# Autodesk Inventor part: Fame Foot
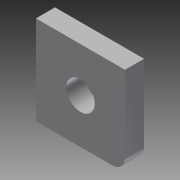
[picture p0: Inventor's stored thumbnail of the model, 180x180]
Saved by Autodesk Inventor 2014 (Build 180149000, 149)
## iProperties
Created: 2007-02
Part Number: Fame Foot
Document SubType Name: Modeling
Designer: Autodesk, Inc.
Density: 7.86 g/cm^3
Material: Steel, Mild
Mass: 135.377 g
Surface Area: 57.0971 cm^2
Volume: 17.2235 cm^3
Appearance: Steel
Title: Plate, Foot
Author: Autodesk, Inc.
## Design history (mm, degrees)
sketch "Sketch1"
  geometry: L1 (12.7, -19.05)-(-22.352, -19.05) reference; L2 (19.05, 22.352)-(19.05, -12.7) reference; L3 (25.4, 25.4)-(22.098, 25.4) reference; L4 (-25.4, -22.098)-(-25.4, -25.4) reference; L5 (19.05, 25.4)-(-25.4, 25.4); L6 (-25.4, -19.05)-(-25.4, 25.4); L7 (19.05, 25.4)-(19.05, -12.7); L8 (-25.4, -19.05)-(12.7, -19.05); A1 r 6.35 centre (12.7, -12.7) between (12.7, -19.05) and (19.05, -12.7) reference
  constraints: 8 end point, 3 perpendicular, 2 collinear, 2 tangent, 1 parallel, 1 point on line
extrude "Extrusion1" new body sketch "Sketch1" distance "d0" = 9.525; taper "d1" = 0 deg
sketch "Sketch2"
  geometry: L1 (-19.05, -12.7)-(-19.05, 25.4) reference; L2 (25.4, -19.05)-(-12.7, -19.05) reference; L3 (25.4, 25.4)-(25.4, -19.05) reference; L4 (-19.05, 25.4)-(25.4, 25.4) reference; L5 (3.175, 25.4)-(3.175, -19.05); L6 (25.4, 3.175)-(-19.05, 3.175); C1 r 7.112 at (3.175, 3.175)
  constraints: 4 end point, 3 midpoint, 2 perpendicular, 2 point on line, 1 centre point
  dimensions: "d2" = 14.224 diameter of C1
extrude "Extrusion2" cut sketch "Sketch2" distance "d3" = 9.525; taper "d4" = 0 deg
body "Solid1"
node "Reference1"
node "Reference2"
node "Reference3"
node "Reference4"
node "Reference5"
